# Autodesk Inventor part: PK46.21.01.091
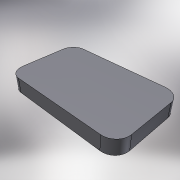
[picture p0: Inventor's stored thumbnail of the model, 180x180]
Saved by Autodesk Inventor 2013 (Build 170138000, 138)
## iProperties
Created: 2005-04
Part Number: PK46.21.01.091
Material: Steel, Mild
Document SubType Name: Modeling
Designer: salex
Manufacturer: Standard
Standards Organization: Custom
Density: 7.86 g/cm^3
Author: salex
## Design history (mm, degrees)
sketch "Эскиз1"
  geometry: L1 (-303.58, 170)-(-50.548, 170) reference; L2 (-303.58, 210)-(-50.548, 210) reference; L3 (0, 1420)-(-250, 1420) reference; L4 (-250, 0)-(-250, 1420) reference; L5 (0, 0)-(-250, 0) reference; L6 (0, 0)-(0, 1420) reference; L7 (-130, 230)-(-30, 230); L8 (-15, 215)-(-15, 165); L9 (-30, 150)-(-130, 150); L10 (-145, 165)-(-145, 215); A1 r 15 centre (-30, 215) between (-15, 215) and (-30, 230); A2 r 15 centre (-30, 165) between (-30, 150) and (-15, 165); A3 r 15 centre (-130, 165) between (-145, 165) and (-130, 150); A4 r 15 centre (-130, 215) between (-130, 230) and (-145, 215)
  constraints: 8 end point, 8 point on circle, 8 tangent, 4 centre point, 3 equal radius, 2 parallel, 1 horizontal, 1 perpendicular
  dimensions: "d0" = 15 radius of A1; "d1" = 20 distance between parallel lines of L2 L7; "d2" = 20 distance between parallel lines of L9 L1 (= d1); "d3" = 15 distance between parallel lines of L8 L6; "d4" = 130 distance between parallel lines of L8 L10
extrude "Выдавливание1" new body sketch "Эскиз1" distance "d5" = 16; taper "d6" = 0 deg
body "Solid1"
node "ЗаимстЛин1"
node "ЗаимстЛин2"
node "ЗаимстЛин3"
